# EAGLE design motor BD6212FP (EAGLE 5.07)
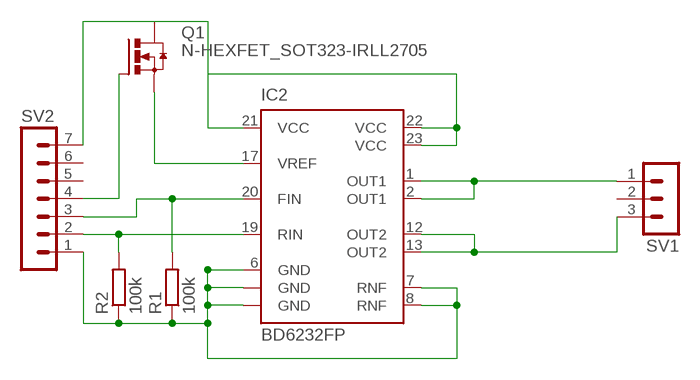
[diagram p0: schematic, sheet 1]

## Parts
IC2  BD6232FP  [HSOP25]
Q1  N-HEXFET_SOT323-IRLL2705  [SOT223]
R1  100k  R-EU_0204/7  [0204/7]
R2  100k  R-EU_0204/7  [0204/7]
SV1  MA03-1  [MA03-1]
SV2  MA07-1  [MA07-1]

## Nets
N$1: IC2.21(VCC) IC2.22(VCC) IC2.23(VCC) Q1.4(D) SV2.7
N$3: IC2.6(GND) IC2.7(RNF) IC2.8(RNF) IC2.GND@1(GND) IC2.GND@2(GND) R1.1 R2.1 SV2.1
N$4: IC2.20(FIN) R1.2 SV2.3
N$5: IC2.19(RIN) R2.2 SV2.2
N$6: Q1.1(G) SV2.4
N$7: IC2.17(VREF) Q1.3(S)
N$8: IC2.1(OUT1) IC2.2(OUT1) SV1.1
N$9: IC2.12(OUT2) IC2.13(OUT2) SV1.3
Unconnected: SV1.2 SV2.5 SV2.6

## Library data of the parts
IC2 = rohm:BD6232FP: H-bridge driver for brush motors Source: http://www.rohm.com/products/databook/motor/pdf/bd623x_series-e.pdf
Q1 = transistor-power:N-HEXFET_?-*: HEXFET® Power MOSFET
R1 R2 = rcl:R-EU_: RESISTOR, European symbol
SV1 = con-lstb:MA03-1: PIN HEADER
SV2 = con-lstb:MA07-1: PIN HEADER

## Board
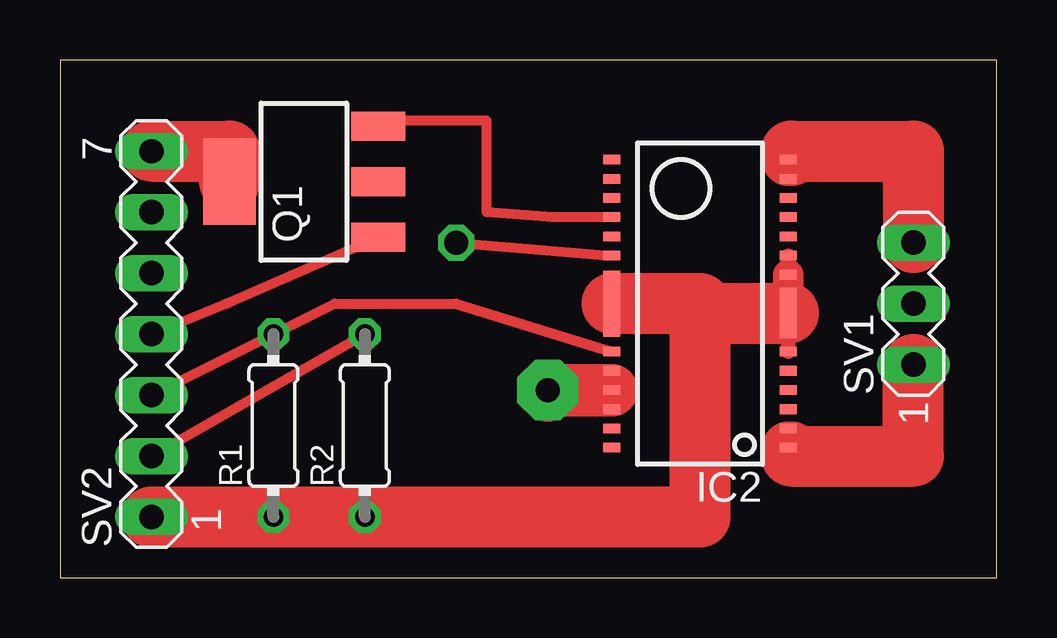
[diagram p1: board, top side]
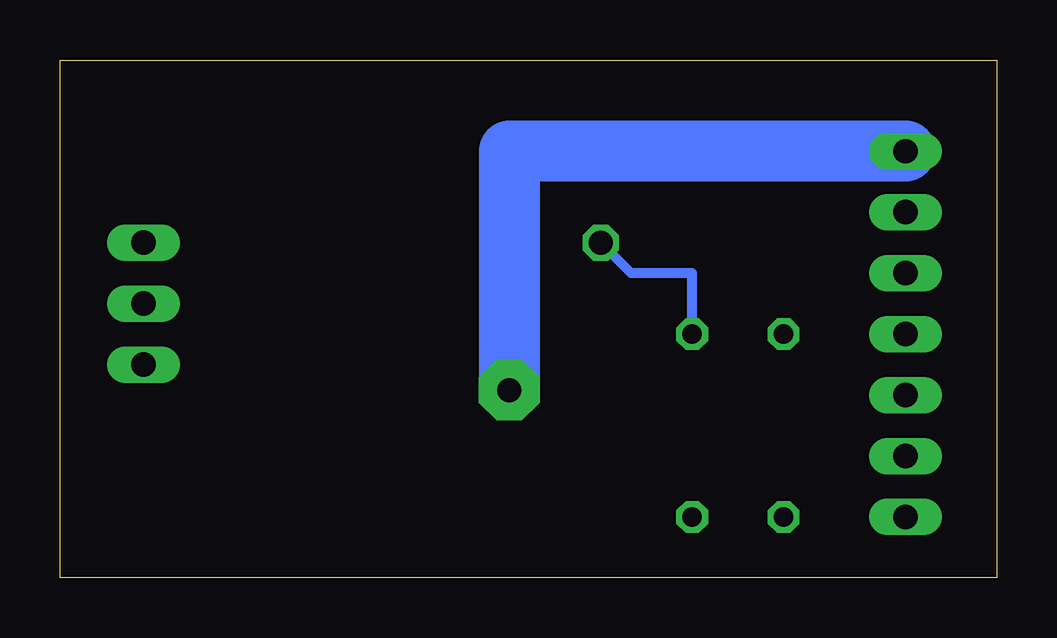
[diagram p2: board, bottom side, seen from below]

Size 39.04 x 21.58 mm. Coordinates in mm from the lower left corner, seen from the top.
Outline: 0,0 39.04,0 39.04,21.58 0,21.58 0,0
Copper layers (1*16): Top 0.035mm / dielectric 1.5mm / Bottom 0.035mm
Design rules "default": minimum track width 10mil, minimum drill 24mil, track to track 8mil, track to pad 8mil, pad to pad 8mil, via to via 8mil, smd to smd 8mil, copper to edge 40mil, drill to drill 8mil, minimum pad ring 10mil, minimum via ring 8mil, stop-mask expansion 4mil, vias tented up to drill 0mil, thermal gap 10mil

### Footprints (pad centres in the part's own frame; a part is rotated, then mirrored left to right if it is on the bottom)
HSOP25 = smd 0.4 x 0.7: 1 -6,-3.675; 2 -5.2,-3.675; 3 -4.4,-3.675; 4 -3.6,-3.675; 5 -2.8,-3.675; 6 -2,-3.675; 7 1.2,-3.675; 8 2,-3.675; 9 2.8,-3.675; 10 3.6,-3.675; 11 4.4,-3.675; 12 5.2,-3.675; 13 6,-3.675; 14 6,3.675; 15 5.2,3.675; 16 4.4,3.675; 17 3.6,3.675; 18 2.8,3.675; 19 2,3.675; 20 -2,3.675; 21 -2.8,3.675; 22 -3.6,3.675; 23 -4.4,3.675; 24 -5.2,3.675; 25 -6,3.675 | smd 2.1 x 0.7: GND@1 -0.4,-3.675 | smd 2.75 x 0.7: GND@2 0,3.675
SOT223 = smd 1.219 x 2.235: 1 -2.311,-3.099; 2 0,-3.099; 3 2.311,-3.099 | smd 3.6 x 2.2: 4 0,3.099
0204/7 = drill 0.813 octagon: 1 -3.81,0; 2 3.81,0
MA03-1 = drill 1.016 long: 1 -2.54,0; 2 0,0; 3 2.54,0
MA07-1 = drill 1.016 long: 1 -7.62,0; 2 -5.08,0; 3 -2.54,0; 4 0,0; 5 2.54,0; 6 5.08,0; 7 7.62,0

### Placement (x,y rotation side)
IC2  26.67,11.43 90 top
Q1  10.16,16.51 90 top
R1  8.89,6.35 90 top
R2  12.7,6.35 90 top
SV1  35.56,11.43 90 top
SV2  3.81,10.16 90 top

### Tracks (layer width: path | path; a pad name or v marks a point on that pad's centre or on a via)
N$1  (via drill 1 pad 2.54)
  Top 0.406: IC2.21 IC2.22 IC2.23
  Top 2.184: IC2.22 v20.32,7.83 20.32,7.62
  Top 2.54: SV2.7 7.06,17.78 Q1.4
  Bottom 2.54: v20.32,7.83 20.32,17.78 SV2.7
N$3
  Top 0.61: IC2.8 IC2.GND@1 IC2.6
  Top 1.27: IC2.GND@1 IC2.7
  Top 2.54: SV2.1 R1.1 R2.1 26.67,2.54 26.67,11.03 | IC2.GND@2 26.67,11.43 26.67,11.03 | 26.67,11.03 IC2.GND@1
N$4
  Top 0.406: SV2.3 R1.2 11.43,11.43 16.51,11.43 IC2.20
N$5  (via drill 1 pad 0.81)
  Top 0.406: SV2.2 R2.2 | v16.51,13.97 IC2.19
  Bottom 0.406: R2.2 12.7,12.7 15.24,12.7 v16.51,13.97
N$6
  Top 0.406: SV2.4 6.91,11.43 Q1.1
N$7
  Top 0.406: IC2.17 20.53,15.03 17.78,15.24 17.78,19.05 13.26,19.05 Q1.3
N$8
  Top 0.406: IC2.2 IC2.1
  Top 2.184: IC2.1 30.48,5.43 30.48,5.08
  Top 2.54: 30.48,5.08 35.56,5.08 SV1.1
N$9
  Top 0.406: IC2.12 IC2.13
  Top 2.184: IC2.13 30.48,17.43 30.48,17.78
  Top 2.54: 30.48,17.78 35.56,17.78 SV1.3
